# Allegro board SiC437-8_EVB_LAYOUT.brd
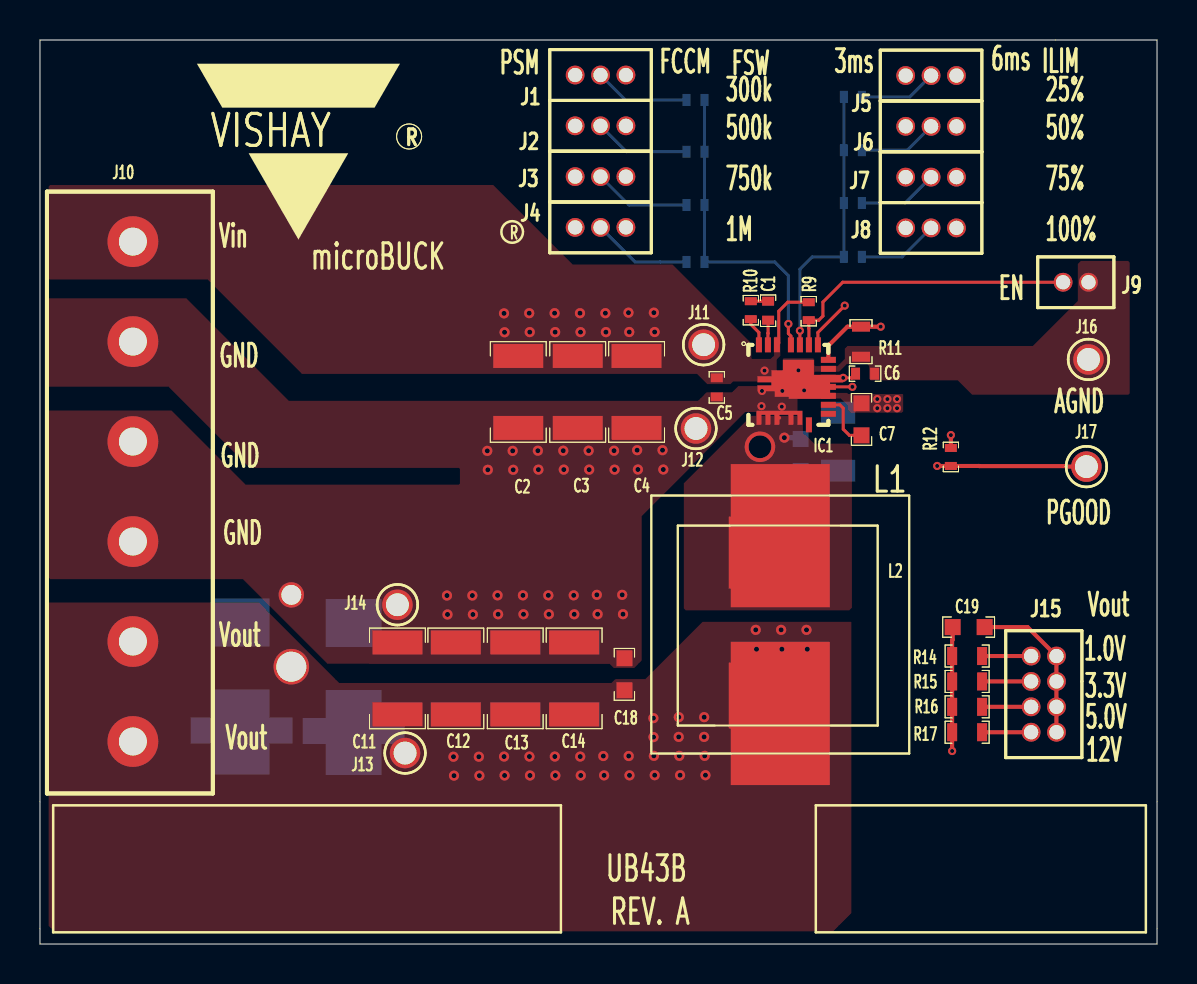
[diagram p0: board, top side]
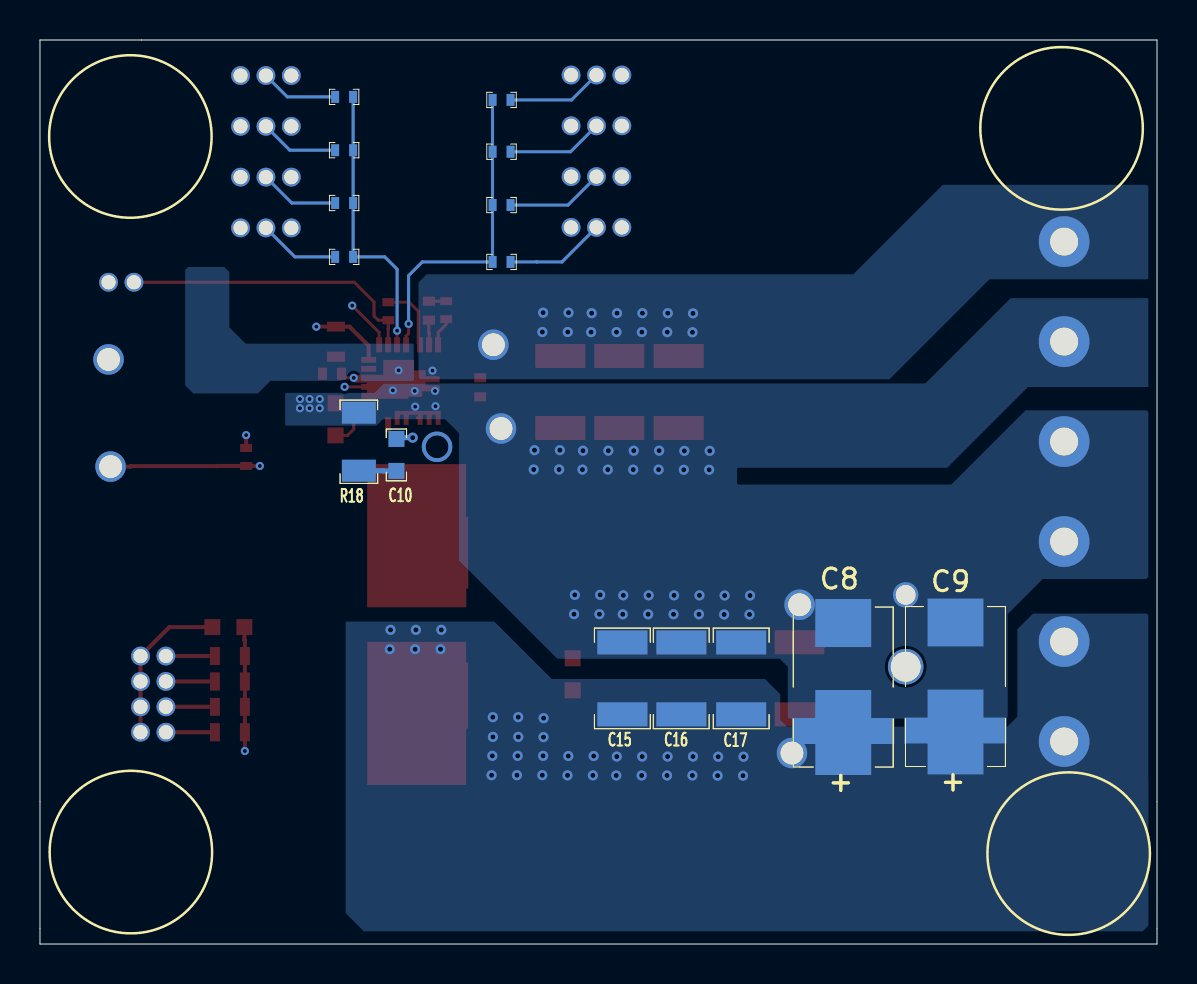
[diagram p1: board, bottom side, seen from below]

Outline 55.88 x 45.21 mm; copper layers: TOP, LAYER2, LAYER3, LAYER4, LAYER5, BOTTOM. Coordinates in mm from the lower left corner of the outline.
Outline path: 0,45.21 0,0 55.88,0 55.88,45.21 0,45.21

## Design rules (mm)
constraint set DEFAULT: min track width 0.152

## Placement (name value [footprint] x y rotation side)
C1  100n  [C0402-TDK1]  36.42 31.67 270 top
C2  22uF  [C1210-TDK]  23.93 27.61 270 top
C3  22uF  [C1210-TDK]  26.9 27.61 270 top
C4  22uF  [C1210-TDK]  29.85 27.61 270 top
C5  0.1uF  [C0402-TDK]  33.86 27.84 270 top
C6  0.1u  [C0402-TDK1]  41.28 28.52 0 top
C7  1u  [C0603-TDK1]  41.1 26.24 90 top
C8  DNP  [POSCAP]  15.7 12.85 90 bottom
C9  DNP  [POSCAP]  10.08 12.88 90 bottom
C10  DNP  [C0603-TDK1]  38.05 24.46 270 bottom
C11  22uF  [C1210-TDK]  17.88 13.28 90 top
C12  22uF  [C1210-TDK]  20.8 13.28 90 top
C13  22uF  [C1210-TDK]  23.77 13.28 90 top
C14  22uF  [C1210-TDK]  26.72 13.28 90 top
C15  22uF  [C1210-TDK]  26.75 13.28 90 bottom
C16  22uF  [C1210-TDK]  23.8 13.28 90 bottom
C17  22uF  [C1210-TDK]  20.8 13.28 90 bottom
C18  0.1u  [C0603-TDK1]  29.24 13.49 90 top
C19  22n  [C0603-TDK1]  46.46 15.85 180 top
IC1  SiC431  [SIC431M]  37.44 27.97 0 top
J1  CON3  [MINIJUMPER3]  29.31 43.46 180 top
J2  CON3  [MINIJUMPER3]  29.31 40.92 180 top
J3  CON3  [MINIJUMPER3]  29.31 38.38 180 top
J4  CON3  [MINIJUMPER3]  29.31 35.84 180 top
J5  CON3  [MINIJUMPER3]  45.85 43.43 180 top
J6  CON3  [MINIJUMPER3]  45.85 40.89 180 top
J7  CON3  [MINIJUMPER3]  45.85 38.35 180 top
J8  CON3  [MINIJUMPER3]  45.85 35.81 180 top
J9  CON2  [MINIJUMPER2]  52.45 33.1 180 top
J10  -  [CON6]  4.65 35.13 270 top
J11  VIN+s  [TP30]  33.2 29.97 0 top
J12  VIN-S  [TP30]  32.82 25.78 0 top
J13  VO+S  [TP30]  18.26 9.55 0 top
J14  VO-S  [TP30]  17.88 16.97 0 top
J15  CON8A  [MINIJUMPER2X4]  49.58 14.4 0 top
J16  AGND  [TP30]  52.45 29.24 0 top
J17  PGOOD  [TP30]  52.35 23.88 0 top
L1  0.22uH  [IHLP]  37.03 15.98 90 top
L2  0.22uH  [HCUVDE1]  36.91 15.93 90 top
NOREF  -  []  12.93 35.23 0 top
PB  CON2  [2PROBE]  12.57 13.87 135 top
R1  51k  [R0402-VISHAY1]  32.79 42.21 180 bottom
R2  100k  [R0402-VISHAY1]  32.79 39.62 180 bottom
R3  200k  [R0402-VISHAY1]  32.79 36.96 180 bottom
R4  510k  [R0402-VISHAY1]  32.79 34.11 180 bottom
R5  51k  [R0402-VISHAY1]  40.67 42.37 0 bottom
R6  100k  [R0402-VISHAY1]  40.67 39.7 0 bottom
R7  200k  [R0402-VISHAY1]  40.67 37.06 0 bottom
R8  510k  [R0402-VISHAY1]  40.67 34.37 0 bottom
R9  100k  [R0402-VISHAY1]  38.46 31.65 90 top
R10  0  [R0402-VISHAY1]  35.56 31.7 270 top
R11  10k  [R0603-VISHAY]  41.07 30.12 90 top
R12  100k  [R0402-VISHAY1]  45.57 24.36 90 top
R14  10k  [R0603-VISHAY]  46.38 14.4 0 top
R15  10k  [R0603-VISHAY]  46.38 13.13 0 top
R16  10k  [R0603-VISHAY]  46.38 11.86 0 top
R17  10k  [R0603-VISHAY]  46.38 10.59 0 top
R18  DNP  [R1206-VISHAY]  39.93 25.12 270 bottom

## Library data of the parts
C1-C6 C11-C19 = CAPACITOR NON-POL
C7 C10 = CAP NP
C8 C9 = POSCAP
IC1 = SiC431_2
J1-J8 = CON3: User Part Number: ***
J9 = CON2: User Part Number: ***
J10 = CON6
J11-J14 J16 J17 = CON1
J15 = CON8A
L1 L2 = INDUCTOR
PB = CON2
R1-R8 R10 R12 R14-R17 = R
R9 R11 R18 = RESISTOR

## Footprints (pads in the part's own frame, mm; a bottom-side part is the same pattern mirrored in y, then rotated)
2PROBE
  round 1.778 hole 1.499: 1(0,0)
  round 1.27 hole 0.991: 2(2.54,-2.54)
C0402-TDK
  rect 0.45x0.6 smd: 1(-0.475,0) 2(0.475,0)
C0402-TDK1
  rect 0.45x0.6 smd: 1(-0.475,0) 2(0.475,0)
C0603-TDK1
  rect 0.8x0.8 smd: 1(-0.8,0) 2(0.8,0)
C1210-TDK
  rect 1.2x2.5 smd: 1(-1.8,0) 2(1.8,0)
CON6
  round 2.54 hole 1.397: 1(0,0) 2(5,0) 3(10,0) 4(15,0) 5(20,0) 6(25,0)
HCUVDE1
  custom 0.9x0.9 smd: 1(-3.65,0) 2(3.65,0)
IHLP
  rect 7.163x4.953 smd: 1(-4.445,0) 2(4.445,0)
MINIJUMPER2
  round 0.94 hole 0.711: 1(0,0) 2(1.27,0)
MINIJUMPER2X4
  round 0.94 hole 0.711: 1(0,0) 2(1.27,0) 3(0,-1.27) 4(1.27,-1.27) 5(0,-2.54) 6(1.27,-2.54) 7(0,-3.81) 8(1.27,-3.81)
MINIJUMPER3
  round 0.94 hole 0.711: 1(0,0) 2(1.27,0) 3(2.54,0)
POSCAP
  rect 2.4x2.8 smd: 1(-3.2,0) 2(3.2,0)
  custom 0.675x0.675 smd: 3(-1.5,0)
R0402-VISHAY1
  rect 0.4x0.6 smd: 1(-0.45,0) 2(0.45,0)
R0603-VISHAY
  rect 0.5x0.9 smd: 1(-0.75,0) 2(0.75,0)
R1206-VISHAY
  rect 1.1x1.7 smd: 1(-1.45,0) 2(1.45,0)
SIC431M
  custom 0.263x0.263 smd: 1(-0.65,0.2)
  round 0 smd: 2(-1.499,0.406) 4(-2.007,-0.914) 6(-0.889,-2.134) 7(-0.432,-2.184) 8(0.076,-2.184) 9(0.457,-2.159)
  custom 0.3x0.3 smd: 3(1.03,-0.1)
  custom 0.175x0.175 smd: 5(-0.45,-1.65)
  rect 0.3x0.75 smd: 10(1.025,-2) 18(1.475,2) 19(1.025,2) 20(0.575,2) 21(0.125,2) 22(-0.575,2) 23(-1.025,2) 24(-1.475,2)
  rect 0.75x0.3 smd: 11(2,-1.45) 12(2,-1) 13(2,-0.55) 14(2,-0.1) 15(2,0.35) 16(2,0.8) 17(2,1.25)
  rect 1.55x1.05 smd: 25(0.5,0.725)
TP30
  round 1.524 hole 1.143: 1(0,0)

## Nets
GND_POWER: C2.2 C3.2 C4.2 C5.2 C6.2 C7.2 C8.2 C8.3 C9.2 C9.3 C11.2 C12.2 C13.2 C14.2 C15.2 C16.2 C17.2 C18.2 IC1.3 IC1.4 IC1.13 IC1.16 IC1.25 J1.3 J2.3 J3.3 J4.3 J5.3 J6.3 J7.3 J8.3 J9.1 J10.2 J10.3 J10.4 J12.1 J14.1 J16.1 PB.2 R11.1 R18.1
VDD1: C6.1 IC1.15 J1.1 J2.1 J3.1 J4.1 J5.1 J6.1 J7.1 J8.1 R12.2
VIN: C2.1 C3.1 C4.1 C5.1 IC1.1 IC1.2 IC1.22 J10.1 J11.1 R9.2
BOOT: C1.2 IC1.23
MODE1: IC1.21 R1.1 R2.1 R3.1 R4.1
MODE2: IC1.20 R5.1 R6.1 R7.1 R8.1
PGD: IC1.14 J17.1 R12.1
PHASE: IC1.24 R10.2
VO: C8.1(P) C9.1(P) C11.1 C12.1 C13.1 C14.1 C15.1 C16.1 C17.1 C18.1 C19.2 IC1.18(VOUT) J10.5 J10.6 J13.1 L1.1 L2.1 PB.1 R14.1 R15.1 R16.1 R17.1
N10425435: C10.1 IC1.5 IC1.6 IC1.7 IC1.8 IC1.9 L1.2 L2.2
N10425735: IC1.19 J9.2 R9.1
N10425943: C1.1 R10.1
N10491860: C19.1 IC1.17 J15.2 J15.4 J15.6 J15.8 R11.2
N10497600: C7.1 IC1.12
N10592056: J1.2 R1.2
N10592279: J2.2 R2.2
N10592308: J3.2 R3.2
N10592330: J4.2 R4.2
N10602058: J5.2 R5.2
N10602062: J6.2 R6.2
N10602066: J7.2 R7.2
N10602070: J8.2 R8.2
N10625993: C10.2 R18.2
N10654889: J15.1 R14.2
N10668036: J15.3 R15.2
N10668228: J15.5 R16.2
N10668284: J15.7 R17.2

Pads without a net: IC1 10 11

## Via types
v1: diameter 1.524, hole 1.143, TOP to BOTTOM, 1 via
v2: diameter 0.508, hole 0.254, TOP to BOTTOM, 81 vias
v3: diameter 0.406, hole 0.203, TOP to BOTTOM, 22 vias

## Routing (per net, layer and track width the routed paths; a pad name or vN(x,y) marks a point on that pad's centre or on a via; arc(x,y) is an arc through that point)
GND_POWER:
  vias: v2(20.36,17.43) v2(20.39,16.48) v2(21.63,17.43) v2(21.66,16.48) v2(22.38,24.66) v2(22.4,23.72) v2(22.89,17.44) v2(22.92,16.49) v2(23.65,24.66) v2(23.67,23.72) v2(24.16,17.44) v2(24.19,16.49) v2(24.91,24.67) v2(24.93,23.73) v2(25.43,17.44) v2(25.46,16.49) v2(26.18,24.67) v2(26.2,23.73) v2(26.7,17.44) v2(26.73,16.49) v2(27.45,24.67) v2(27.47,23.73) v2(27.86,17.46) v2(27.9,16.5) v2(28.72,24.67) v2(28.74,23.73) v2(29.13,17.46) v2(29.17,16.5) v2(29.87,24.7) v2(29.91,23.73) v2(31.14,24.7) v2(31.18,23.73) v3(36.12,27.66) v3(36.09,26.9) v3(37.13,27.66) v3(37.11,26.87) v3(37.94,28.69) v3(38.23,27.69) v3(41.88,27.25) v3(41.88,26.8) v3(42.39,27.25) v3(42.39,26.8) v3(42.88,27.25) v3(42.88,26.8)
VDD1: length 49.7
  TOP w0.152: 40.59,28.32 v3(40.18,28.32) IC1.15 ; 40.59,28.32 40.79,28.52 40.79,28.52 ; 40.59,28.32 40.59,28.32 C6.1
  TOP w0.203: R12.2 v3(45.57,25.45)
  LAYER3 w0.152: J5.1 J6.1 J7.1 J8.1 45.85,34.24 45.26,33.66 40.72,33.66 39.68,32.62 39.68,31.49 ; 39.68,31.49 37.06,34.11 31.04,34.11 J4.1 J3.1 J2.1 J1.1 ; 39.68,31.49 40.18,30.99 v3(40.18,28.32) 43.36,28.32 45.57,26.11 v3(45.57,25.45)
VIN: length 3.4
  TOP w0.152: R9.2 37.41,32.1 36.96,31.65 36.96,30.06 IC1.22
  vias: v2(23.21,31.54) v2(23.24,30.59) v2(24.47,31.55) v2(24.5,30.6) v2(25.74,31.55) v2(25.77,30.6) v2(27.01,31.55) v2(27.04,30.6) v2(28.28,31.55) v2(28.31,30.6) v2(29.44,31.57) v2(29.48,30.61) v2(30.71,31.57) v2(30.75,30.61) v3(36.25,28.68)
BOOT: length 1.2
  TOP w0.152: C1.2 36.42,30.54 36.41,30.54 IC1.23
MODE1: length 16.1
  TOP w0.152: v3(37.44,31.01) 37.44,30.53 37.56,30.41 IC1.21
  BOTTOM w0.152: v3(37.44,31.01) 37.44,33.43 36.75,34.11 R4.1 R3.1 R2.1 R1.1
MODE2: length 14.2
  TOP w0.152: IC1.20 v3(38.01,30.67)
  BOTTOM w0.152: v3(38.01,30.67) 38.01,33.75 38.63,34.37 R8.1 R7.1 R6.1 R5.1
PGD: length 16
  TOP w0.152: v3(40.64,27.87) IC1.14
  TOP w0.203: v3(44.88,23.91) R12.1 46.98,23.91 46.99,23.9 51.33,23.9 51.36,23.88 J17.1
  LAYER3 w0.152: v3(40.64,27.87) 43.31,27.87 44.88,26.29 v3(44.88,23.91)
PHASE: length 1.5
  TOP w0.152: IC1.24 35.96,30.58 35.56,30.99 R10.2
VO: length 63.2
  TOP w0.152: v3(40.26,31.93) 38.91,30.58 IC1.18
  TOP w0.203: v3(45.63,9.65) R17.1 R16.1 R15.1 R14.1 45.63,15.19 45.66,15.22 C19.2
  LAYER3 w0.152: J13.1 20.02,7.8 44.88,7.8 45.63,8.55 v3(45.63,9.65) 46.23,10.25 46.23,25.96 v3(40.26,31.93)
  vias: v2(20.68,9.37) v2(20.71,8.42) v2(21.95,9.37) v2(21.98,8.42) v2(23.22,9.38) v2(23.24,8.43) v2(24.49,9.38) v2(24.51,8.43) v2(25.76,9.38) v2(25.78,8.43) v2(27.03,9.38) v2(27.05,8.43) v2(28.18,9.4) v2(28.22,8.43) v2(29.45,9.4) v2(29.49,8.43) v2(30.69,11.3) v2(30.69,10.35) v2(30.71,9.41) v2(30.75,8.44) v2(31.96,11.35) v2(31.95,10.36) v2(31.98,9.41) v2(32.02,8.44) v2(33.23,11.35) v2(33.22,10.36) v2(33.25,9.41) v2(33.29,8.44) v2(35.8,15.71) v2(35.84,14.74) v2(37.07,15.71) v2(37.11,14.74) v2(38.34,15.71) v2(38.38,14.74)
N10425435: length 0.8
  BOTTOM w0.254: C10.1 37.99,25.32 v2(37.24,25.32)
  vias: v1(36.02,24.87)
N10425735: length 15.2
  TOP w0.152: J9.2 40.16,33.1 39.17,32.11 39.17,31.41 38.96,31.2 R9.1 38.46,30.8 38.46,30.79 IC1.19
N10425943: length 0.9
  TOP w0.152: C1.1 R10.1
N10491860: length 31.8
  TOP w0.203: C19.1 49.4,15.85 J15.2 J15.4 J15.6 J15.8 ; v3(42.06,30.87) R11.2 40.39,30.87 39.44,29.92 IC1.17
  LAYER3 w0.152: v3(42.06,30.87) 50.85,22.08 J15.2
N10497600: length 2.9
  TOP w0.152: C7.1 40.49,25.44 40.18,25.75 40.18,26.8 40.02,26.97 IC1.12
N10592056: length 4.8
  BOTTOM w0.152: R1.2 29.29,42.21 J1.2
N10592279: length 4.8
  BOTTOM w0.152: J2.2 29.34,39.62 R2.2
N10592308: length 4.9
  BOTTOM w0.152: J3.2 29.46,36.96 R3.2
N10592330: length 5
  BOTTOM w0.152: 31.02,34.11 29.77,34.11 J4.2 ; 31.02,34.11 31.02,34.13 ; 31.02,34.11 R4.2
N10602058: length 3.9
  BOTTOM w0.152: J5.2 43.51,42.37 R5.2
N10602062: length 4
  BOTTOM w0.152: R6.2 43.38,39.7 J6.2
N10602066: length 4
  BOTTOM w0.152: J7.2 43.28,37.06 R7.2
N10602070: length 4.1
  BOTTOM w0.152: J8.2 43.13,34.37 R8.2
N10625993: length 1.9
  BOTTOM w0.254: C10.2 38.7,23.66 38.71,23.67 R18.2
N10654889: length 2.5
  TOP w0.203: J15.1 R14.2
N10668036: length 2.5
  TOP w0.203: J15.3 R15.2
N10668228: length 2.5
  TOP w0.203: J15.5 R16.2
N10668284: length 2.5
  TOP w0.203: J15.7 R17.2

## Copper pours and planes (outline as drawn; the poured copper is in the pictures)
GND_POWER on TOP: outline of 82 points within 0.43,13.8 54.51,34.16
GND_POWER on BOTTOM: 7.32,32.3 11.58,28.04 38.66,28.04 39.14,27.56 43.59,27.56 43.61,27.53 43.61,25.96 43.58,25.93 39.04,25.93 38.72,26.24 35.61,26.24 34.91,25.55 34.91,19.18 30,14.27 18.87,14.27 18.47,13.86 18.47,11.35 18.39,11.27 7.57,11.27 7.47,11.37 7.47,16.5 5.72,18.26 0.54,18.26 0.43,18.36 0.43,26.61 0.51,26.69 6.58,26.69 10.29,22.98 20.96,22.98 21.01,23.03 21.01,23.77 20.96,23.82 10.49,23.82 6.45,27.86 0.43,27.86 0.43,32.25 0.48,32.3
GND_POWER on BOTTOM: 37.19,28.19 37.19,30 37.21,30.02 45.59,30.02 46.41,30.84 46.41,33.6 46.66,33.86 48.46,33.86 48.62,33.71 48.62,27.94 48.21,27.53 44.98,27.53 44.35,28.17 37.21,28.17
GND_POWER on LAYER2: 28.05,32.31 32.44,27.91 40.94,27.91 44.88,27.91 45.16,27.64 45.16,23.7 48.8,20.07 48.8,8.38 48.79,8.38 48.79,0.71 48.54,0.46 0.74,0.46 0.44,0.76 0.44,26.65 0.48,26.69 6.61,26.69 10.31,22.99 20.96,22.99 21.01,23.04 21.01,23.78 20.97,23.82 10.52,23.82 6.5,27.84 0.54,27.84 0.44,27.95 0.44,32.26 0.48,32.31
GND_POWER on LAYER2: 25.48,44.78 27.08,44.78 27.31,44.55 27.31,34.98 27.64,34.65 35.85,34.65 36.66,35.46 36.66,44.81 43.66,44.81 43.87,44.6 43.87,28.57 43.71,28.42 37.49,28.42 32.89,33.02 25.61,33.02 24.97,33.65 24.97,44.27
GND_POWER on LAYER3: 28.02,32.31 32.41,27.91 39.5,27.91 39.9,27.51 43.21,27.51 44.27,26.44 44.27,1.63 43.64,0.99 1.32,0.99 0.43,1.88 0.43,26.64 0.48,26.7 6.58,26.7 10.29,22.99 20.96,22.99 21.01,23.04 21.01,23.77 20.96,23.83 10.49,23.83 6.48,27.84 0.53,27.84 0.43,27.94 0.43,32.26 0.48,32.31
GND_POWER on LAYER4: 28.04,32.3 32.44,27.91 44.08,27.91 44.5,27.48 44.5,24.35 48.46,20.39 48.46,1.75 47.02,0.3 0.69,0.3 0.43,0.56 0.43,26.64 0.48,26.69 6.6,26.69 10.31,22.99 20.96,22.99 21.01,23.04 21.01,23.77 20.96,23.82 10.52,23.82 6.5,27.84 0.53,27.84 0.43,27.94 0.43,32.26 0.48,32.3
GND_POWER on LAYER4: 14.61,44.55 19.74,44.55 19.94,44.35 19.94,34.79 20.32,34.41 24.97,34.41 25.78,35.22 25.78,44.57 39.05,44.57 39.27,44.35 39.27,28.72 38.76,28.21 32.84,28.21 28.27,32.79 14.73,32.79 14.1,33.42 14.1,44.04
GND_POWER on LAYER5: 7.32,32.31 11.58,28.04 43.56,28.04 43.61,27.99 43.61,25.91 43.56,25.86 35.05,25.86 34.75,25.55 34.75,18.85 29.92,14.02 14.43,14.02 10.19,18.26 0.51,18.26 0.43,18.34 0.43,26.67 0.46,26.7 6.58,26.7 10.29,22.99 20.96,22.99 21.01,23.04 21.01,23.77 20.96,23.83 10.49,23.83 6.43,27.89 0.46,27.89 0.43,27.91 0.43,32.28 0.46,32.31
VIN on TOP: 22.67,37.96 26.65,33.98 31.64,33.98 35.59,30.03 35.59,29.3 35.63,29.26 36.55,29.26 36.73,29.44 36.73,30.35 36.75,30.38 37.01,30.38 37.03,30.35 37.03,29.41 36.96,29.34 36.86,29.24 36.86,28.16 36.83,28.13 34.67,28.13 34.55,28 33.38,28 32.87,28.51 13.11,28.51 8.38,33.24 0.48,33.24 0.43,33.29 0.43,37.88 0.51,37.96
VIN on BOTTOM: 10.72,37.97 15.19,33.5 36.53,33.5 36.94,33.08 36.94,28.35 36.84,28.24 13.38,28.24 8.38,33.24 0.48,33.24 0.43,33.29 0.43,37.89 0.51,37.97
VIN on LAYER5: 10.72,37.97 14.69,34 31.64,34 35.26,30.38 37.03,30.38 37.06,30.35 37.06,28.19 37.03,28.17 13.46,28.17 8.38,33.25 0.48,33.25 0.43,33.3 0.43,37.9 0.51,37.97
VO on TOP: 33.15,16.12 30.28,13.25 28.78,13.25 28.59,13.06 14.96,13.06 10.94,17.08 0.46,17.08 0.43,17.06 0.43,0.91 0.71,0.64 39.67,0.64 40.59,1.55 40.59,16.09 40.57,16.12
VO on BOTTOM: 33.15,16.12 30.28,13.25 19.61,13.25 18.85,12.49 18.85,11.2 18.52,10.87 7.5,10.87 6.99,11.37 6.99,15.74 6.2,16.53 0.51,16.53 0.43,16.45 0.43,8.22 0.43,8.22 0.43,0.91 0.71,0.64 39.67,0.64 40.59,1.55 40.59,16.1 40.57,16.12
VO on LAYER5: 33.15,16.13 30.34,13.32 14.52,13.32 10.74,17.09 0.46,17.09 0.43,17.07 0.43,7.8 0.46,7.77 0.46,0.86 0.76,0.56 39.73,0.56 40.59,1.42 40.59,16.1 40.56,16.13
N10425435 on TOP: 35.59,26.42 38.13,26.42 38.18,26.37 38.18,25.58 38.73,25.02 40.46,25.02 40.61,24.87 40.61,16.81 40.49,16.69 32.31,16.69 32.21,16.79 32.21,23.04

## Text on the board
Ref Des/Silkscreen Top: R | Vin | Vout | GND | PSM | FCCM | 300k | 500k | 750k | 1M | FSW | 3ms | 6ms | EN | ILIM | 25% | 50% | 75% | 100% | PGOOD | AGND | 1.0V | 3.3V | 5.0V | 12V | microBUCK | UB43B | REV. A
FAB: Layer4 | Layer3 | Layer2 | Layer5 | Bottom | Top | TOTAL THICKNESS - 0.62 -.008/+.005 | 2OZ | 1 THIS IS A 6 LAYER BOARD WITH COMPONENTS ON BOTH SIDES. | 3 SILKSCREEN BOTH SIDES WITH WHITE NON CONDUCTIVE EPOXY BASED INK | 4 IMMERSION GOLD FINISH | 2 SMT LAND PATTERNS THAT HAVE A FINISHED PAD WIDTH RANGING FROM | 6 Material Type: IT175A | 5 RED SOLDER MASK | .012 TO .015 MUST USE THE FOLLOWING TOLERANCE, +.002-.0005. | PB VENDOR TO ADJUST ARTWORK TO COMPENSATE FOR ETCH PROCESS. | NOTES: UNLESS OTHERWISE SPECIFIED:
